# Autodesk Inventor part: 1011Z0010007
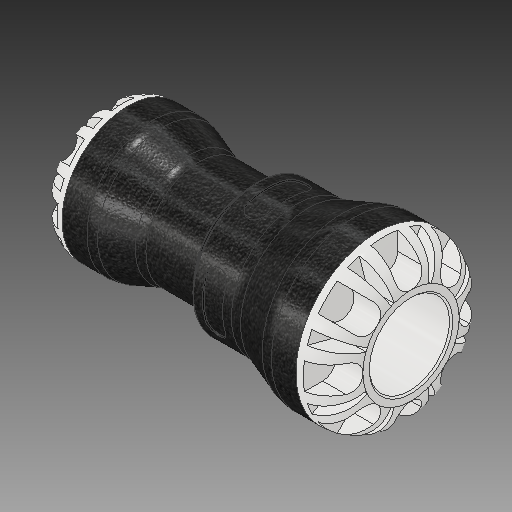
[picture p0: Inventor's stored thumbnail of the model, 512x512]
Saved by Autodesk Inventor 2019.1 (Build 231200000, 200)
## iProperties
Created: 2016-12
Part Number: 1011Z0010007
Material: PVC-Piping
Description: PLASSON REDUCING COUPLING 1''CTS x 3/4''CTS SERIES 1
Document SubType Name: Modeling
Designer: KIM
Mass: 309.689 g
Surface Area: 488.063 cm^2
Volume: 221.206 cm^3
Density: 1.4 g/cm^3
Appearance: Black Cast
Author: KIM
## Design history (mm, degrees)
derived "1011Z.ipt"
feature "Solid1::1011Z.ipt"
tag "TaggingFeature1"
body "Solid1"
other parameters: "d_" = 28.45, "d1" = 22.1, "E_" = 57.912, "H_" = 109.982, "l_" = 53.848, "E1" = 46.99, "l1" = 48.006, "d20" = 9.6825, "d21" = 11.886, "d23" = 57.912, "d24" = 34.14, "d40" = 46.99, "d41" = 27.625, "d59" = 13.44335, "d0" = 109.982, "d2" = 22.61616, "d3" = 28.45, "d4" = 57.912, "d5" = 34.14, "d6" = 53.848, "d7" = 2.37083, "d8" = 46.99, "d9" = 22.1, "d10" = 27.625, "d11" = 20.16252, "d12" = 48.006, "d13" = 1.84167, "d14" = 46.3296, "d15" = 37.592, "d16" = 20 deg, "d17" = 20 deg, "d18" = 130 deg, "d22" = 9.5088, "d25" = 9.5088, "d26" = 0, "d28" = 360 deg, "d30" = 8 deg, "d31" = 0.569, "d32" = 8 deg, "d33" = 0.569, "d35" = 0, "d37" = 360 deg, "d39" = 7.746, "d42" = 7.746, "d43" = 0, "d45" = 360 deg, "d47" = 0.442, "d48" = 8 deg, "d49" = 8 deg, "d50" = 0.442, "d52" = 0, "d54" = 360 deg, "d56" = 9.398, "d57" = 11.5824, "d58" = 0.5, "d60" = 6.94944, "d61" = 7.1125, "d62" = 16.09164, "d63" = 0, "d66" = 0, "d68" = 360 deg, "d75" = 6.72167, "d77" = 45.17136, "d78" = 0.57912
